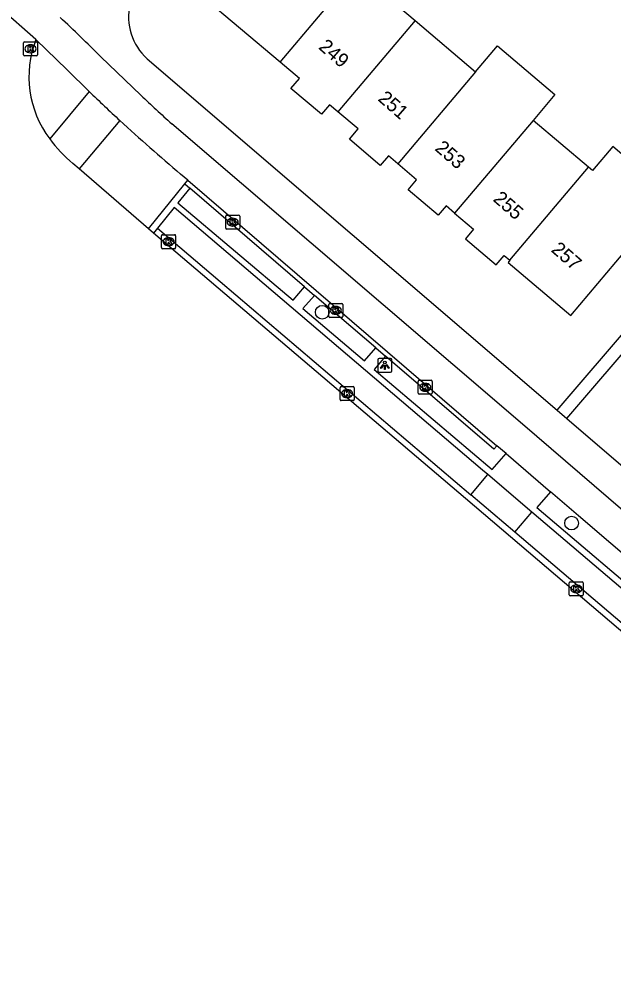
# Model space of a CAD drawing. Extents: x 162532 to 163264, y 381233 to 382042.
# Drawn here: x 162699.1 to 162741.6, y 381608.8 to 381676.6 of the extents above; entities that cross this region are included whole.
import ezdxf

# ---------------------------------------------------------------- set-up
doc = ezdxf.new("R2010")
doc.units = 0
for name, color, linetype in [('IMGEO_Berm_groen', 7, 'Continuous'), ('IMGEO_Berm_open', 7, 'Continuous'), ('IMGEO_Boom', 7, 'Continuous'), ('IMGEO_Fietspad_gesloten', 7, 'Continuous'), ('IMGEO_Groenvoorziening', 7, 'Continuous'), ('IMGEO_Kolk', 7, 'Continuous'), ('IMGEO_Lichtpunt', 7, 'Continuous'), ('IMGEO_Pand', 7, 'Continuous'), ('IMGEO_Pand_nummerreeks', 7, 'Continuous'), ('IMGEO_Parkeervlak_open', 7, 'Continuous'), ('IMGEO_Rijbaan_lokaal_gesloten', 7, 'Continuous'), ('IMGEO_Rijbaan_lokaal_open', 7, 'Continuous'), ('IMGEO_Voetpad_open', 7, 'Continuous')]:
    doc.layers.add(name, color=color, linetype=linetype)

msp = doc.modelspace()

# ---------------------------------------------------------------- linework, layer by layer
at = {"layer": 'IMGEO_Berm_groen'}
for points in [[(162719.505, 381657.491), (162711.294, 381664.536)], [(162724.61, 381653.11), (162720.224, 381656.874)], [(162733.256, 381646.123), (162733.039, 381645.878), (162725.293, 381652.525)]]:
    msp.add_lwpolyline(points, dxfattribs=at)
at = {"layer": 'IMGEO_Berm_open'}
for points in [[(162708.35, 381661.621), (162710.941, 381664.839)], [(162710.941, 381664.839), (162711.294, 381664.536)], [(162711.294, 381664.536), (162710.447, 381663.496), (162718.691, 381656.531), (162719.505, 381657.491)], [(162719.505, 381657.491), (162720.224, 381656.874)], [(162720.224, 381656.874), (162719.381, 381655.936), (162723.796, 381652.18), (162724.61, 381653.11)], [(162725.293, 381652.525), (162724.485, 381651.57), (162732.918, 381644.414), (162733.918, 381645.555)], [(162724.61, 381653.11), (162725.293, 381652.525)], [(162735.765, 381641.379), (162732.619, 381644.053)], [(162737.109, 381642.818), (162736.116, 381641.702), (162745.098, 381634.067), (162746.03, 381635.17)]]:
    msp.add_lwpolyline(points, dxfattribs=at)
at = {"layer": 'IMGEO_Boom'}
for centre in [(162720.767, 381655.666), (162738.609, 381640.586)]:
    msp.add_circle(centre, 0.489, dxfattribs=at)
at = {"layer": 'IMGEO_Fietspad_gesloten'}
for points in [[(162704.102, 381671.452), (162702.525, 381673.004), (162700.289, 381675.168)], [(162707.801, 381671.186), (162704.925, 381673.932)], [(162862.139, 381539.717), (162835.26, 381562.126), (162827.852, 381568.349), (162795.857, 381595.619), (162764.671, 381622.232), (162735.085, 381647.652), (162710.008, 381669.138)], [(162711.156, 381665.102), (162710.64, 381665.545)], [(162711.156, 381665.102), (162733.256, 381646.123)], [(162733.918, 381645.555), (162733.256, 381646.123)], [(162733.918, 381645.555), (162737.109, 381642.818)], [(162746.03, 381635.17), (162739.101, 381641.11), (162737.109, 381642.818)]]:
    msp.add_lwpolyline(points, dxfattribs=at)
for centre, radius, start, end in [((162633.194, 381602.874), 100.968, 44.73005, 47.02968), ((162794.077, 381764.47), 129.414, 225.95289, 227.29117), ((162783.492, 381750.54), 109.664, 226.35347, 227.92658), ((162792.908, 381763.14), 127.643, 227.27156, 229.87063)]:
    msp.add_arc(centre, radius, start, end, dxfattribs=at)
at = {"layer": 'IMGEO_Groenvoorziening'}
msp.add_lwpolyline([(162710.941, 381664.839), (162711.156, 381665.102)], dxfattribs=at)
at = {"layer": 'IMGEO_Kolk'}
for p, q in [((162699.404, 381674.081), (162699.404, 381674.933)), ((162699.479, 381675.007), (162700.331, 381675.007)), ((162700.405, 381674.933), (162700.405, 381674.081)), ((162699.915, 381674.227), (162699.89, 381674.227)), ((162699.892, 381674.787), (162699.917, 381674.787)), ((162700.331, 381674.007), (162699.479, 381674.007)), ((162713.864, 381661.68), (162713.864, 381662.532)), ((162713.939, 381662.606), (162714.791, 381662.606)), ((162714.352, 381662.386), (162714.377, 381662.386)), ((162714.865, 381662.532), (162714.865, 381661.68)), ((162714.791, 381661.606), (162713.939, 381661.606)), ((162714.375, 381661.826), (162714.35, 381661.826)), ((162709.285, 381660.286), (162709.285, 381661.138)), ((162709.36, 381661.212), (162710.212, 381661.212)), ((162709.773, 381660.992), (162709.798, 381660.992)), ((162710.286, 381661.138), (162710.286, 381660.286)), ((162710.212, 381660.212), (162709.36, 381660.212)), ((162709.796, 381660.432), (162709.771, 381660.432)), ((162721.239, 381655.373), (162721.239, 381656.225)), ((162721.314, 381656.299), (162722.166, 381656.299)), ((162721.727, 381656.079), (162721.752, 381656.079)), ((162722.24, 381656.225), (162722.24, 381655.373)), ((162722.166, 381655.299), (162721.314, 381655.299)), ((162721.75, 381655.519), (162721.725, 381655.519)), ((162727.641, 381649.872), (162727.641, 381650.724)), ((162727.716, 381650.798), (162728.568, 381650.798)), ((162728.129, 381650.578), (162728.154, 381650.578)), ((162728.642, 381650.724), (162728.642, 381649.872)), ((162722.051, 381649.418), (162722.051, 381650.27)), ((162722.126, 381650.344), (162722.978, 381650.344)), ((162722.539, 381650.124), (162722.564, 381650.124)), ((162723.052, 381650.27), (162723.052, 381649.418)), ((162728.568, 381649.798), (162727.716, 381649.798)), ((162728.152, 381650.018), (162728.127, 381650.018)), ((162722.978, 381649.344), (162722.126, 381649.344)), ((162722.562, 381649.564), (162722.537, 381649.564)), ((162738.442, 381635.461), (162738.442, 381636.313)), ((162738.517, 381636.387), (162739.369, 381636.387)), ((162739.443, 381636.313), (162739.443, 381635.461)), ((162738.953, 381635.607), (162738.928, 381635.607)), ((162738.93, 381636.167), (162738.955, 381636.167)), ((162739.369, 381635.387), (162738.517, 381635.387))]:
    msp.add_line(p, q, dxfattribs=at)
for points in [[(162699.404, 381674.081), (162699.404, 381674.933)], [(162699.479, 381675.007), (162700.331, 381675.007)], [(162700.405, 381674.933), (162700.405, 381674.081)], [(162699.725, 381674.707), (162699.848, 381674.707), (162699.848, 381674.556), (162699.978, 381674.707), (162700.142, 381674.707), (162699.996, 381674.556), (162700.149, 381674.307), (162699.997, 381674.307), (162699.912, 381674.471), (162699.848, 381674.404), (162699.848, 381674.307), (162699.725, 381674.307), (162699.725, 381674.707)], [(162700.331, 381674.007), (162699.479, 381674.007)], [(162713.864, 381661.68), (162713.864, 381662.532)], [(162713.939, 381662.606), (162714.791, 381662.606)], [(162714.185, 381662.306), (162714.308, 381662.306), (162714.308, 381662.155), (162714.438, 381662.306), (162714.602, 381662.306), (162714.456, 381662.155), (162714.609, 381661.906), (162714.457, 381661.906), (162714.372, 381662.07), (162714.308, 381662.003), (162714.308, 381661.906), (162714.185, 381661.906), (162714.185, 381662.306)], [(162714.865, 381662.532), (162714.865, 381661.68)], [(162714.791, 381661.606), (162713.939, 381661.606)], [(162709.285, 381660.286), (162709.285, 381661.138)], [(162709.36, 381661.212), (162710.212, 381661.212)], [(162709.606, 381660.912), (162709.729, 381660.912), (162709.729, 381660.761), (162709.859, 381660.912), (162710.023, 381660.912), (162709.877, 381660.761), (162710.03, 381660.512), (162709.878, 381660.512), (162709.793, 381660.676), (162709.729, 381660.609), (162709.729, 381660.512), (162709.606, 381660.512), (162709.606, 381660.912)], [(162710.286, 381661.138), (162710.286, 381660.286)], [(162710.212, 381660.212), (162709.36, 381660.212)], [(162721.239, 381655.373), (162721.239, 381656.225)], [(162721.314, 381656.299), (162722.166, 381656.299)], [(162721.56, 381655.999), (162721.683, 381655.999), (162721.683, 381655.848), (162721.813, 381655.999), (162721.977, 381655.999), (162721.831, 381655.848), (162721.984, 381655.599), (162721.832, 381655.599), (162721.747, 381655.763), (162721.683, 381655.696), (162721.683, 381655.599), (162721.56, 381655.599), (162721.56, 381655.999)], [(162722.24, 381656.225), (162722.24, 381655.373)], [(162722.166, 381655.299), (162721.314, 381655.299)], [(162727.641, 381649.872), (162727.641, 381650.724)], [(162727.716, 381650.798), (162728.568, 381650.798)], [(162727.962, 381650.498), (162728.085, 381650.498), (162728.085, 381650.347), (162728.215, 381650.498), (162728.379, 381650.498), (162728.233, 381650.347), (162728.386, 381650.098), (162728.234, 381650.098), (162728.149, 381650.262), (162728.085, 381650.195), (162728.085, 381650.098), (162727.962, 381650.098), (162727.962, 381650.498)], [(162728.642, 381650.724), (162728.642, 381649.872)], [(162722.051, 381649.418), (162722.051, 381650.27)], [(162722.126, 381650.344), (162722.978, 381650.344)], [(162722.372, 381650.044), (162722.495, 381650.044), (162722.495, 381649.893), (162722.625, 381650.044), (162722.789, 381650.044), (162722.643, 381649.893), (162722.796, 381649.644), (162722.644, 381649.644), (162722.559, 381649.808), (162722.495, 381649.741), (162722.495, 381649.644), (162722.372, 381649.644), (162722.372, 381650.044)], [(162723.052, 381650.27), (162723.052, 381649.418)], [(162728.568, 381649.798), (162727.716, 381649.798)], [(162722.978, 381649.344), (162722.126, 381649.344)], [(162738.442, 381635.461), (162738.442, 381636.313)], [(162738.517, 381636.387), (162739.369, 381636.387)], [(162739.443, 381636.313), (162739.443, 381635.461)], [(162738.763, 381636.087), (162738.886, 381636.087), (162738.886, 381635.936), (162739.016, 381636.087), (162739.18, 381636.087), (162739.034, 381635.936), (162739.187, 381635.687), (162739.035, 381635.687), (162738.95, 381635.851), (162738.886, 381635.784), (162738.886, 381635.687), (162738.763, 381635.687), (162738.763, 381636.087)], [(162739.369, 381635.387), (162738.517, 381635.387)]]:
    msp.add_lwpolyline(points, dxfattribs=at)
for centre, start, end in [((162699.481, 381674.931), 91.55205, 178.44795), ((162699.481, 381674.931), 91.55205, 178.44795), ((162700.329, 381674.931), 1.55205, 88.44795), ((162700.329, 381674.931), 1.55205, 88.44795), ((162699.481, 381674.083), 181.55205, 268.44795), ((162699.481, 381674.083), 181.55205, 268.44795), ((162700.329, 381674.083), 271.55205, 358.44795), ((162700.329, 381674.083), 271.55205, 358.44795), ((162713.941, 381662.53), 91.55205, 178.44795), ((162713.941, 381662.53), 91.55205, 178.44795), ((162714.789, 381662.53), 1.55205, 88.44795), ((162714.789, 381662.53), 1.55205, 88.44795), ((162713.941, 381661.682), 181.55205, 268.44795), ((162713.941, 381661.682), 181.55205, 268.44795), ((162714.789, 381661.682), 271.55205, 358.44795), ((162714.789, 381661.682), 271.55205, 358.44795), ((162709.362, 381661.136), 91.55205, 178.44795), ((162709.362, 381661.136), 91.55205, 178.44795), ((162710.21, 381661.136), 1.55205, 88.44795), ((162710.21, 381661.136), 1.55205, 88.44795), ((162709.362, 381660.288), 181.55205, 268.44795), ((162709.362, 381660.288), 181.55205, 268.44795), ((162710.21, 381660.288), 271.55205, 358.44795), ((162710.21, 381660.288), 271.55205, 358.44795), ((162721.316, 381656.223), 91.55205, 178.44795), ((162721.316, 381656.223), 91.55205, 178.44795), ((162722.164, 381656.223), 1.55205, 88.44795), ((162722.164, 381656.223), 1.55205, 88.44795), ((162721.316, 381655.375), 181.55205, 268.44795), ((162721.316, 381655.375), 181.55205, 268.44795), ((162722.164, 381655.375), 271.55205, 358.44795), ((162722.164, 381655.375), 271.55205, 358.44795), ((162727.718, 381650.722), 91.55205, 178.44795), ((162727.718, 381650.722), 91.55205, 178.44795), ((162728.566, 381650.722), 1.55205, 88.44795), ((162728.566, 381650.722), 1.55205, 88.44795), ((162722.128, 381650.268), 91.55205, 178.44795), ((162722.128, 381650.268), 91.55205, 178.44795), ((162722.976, 381650.268), 1.55205, 88.44795), ((162722.976, 381650.268), 1.55205, 88.44795), ((162727.718, 381649.874), 181.55205, 268.44795), ((162727.718, 381649.874), 181.55205, 268.44795), ((162728.566, 381649.874), 271.55205, 358.44795), ((162728.566, 381649.874), 271.55205, 358.44795), ((162722.128, 381649.42), 181.55205, 268.44795), ((162722.128, 381649.42), 181.55205, 268.44795), ((162722.976, 381649.42), 271.55205, 358.44795), ((162722.976, 381649.42), 271.55205, 358.44795), ((162738.519, 381636.311), 91.55205, 178.44795), ((162738.519, 381636.311), 91.55205, 178.44795), ((162739.367, 381636.311), 1.55205, 88.44795), ((162739.367, 381636.311), 1.55205, 88.44795), ((162738.519, 381635.463), 181.55205, 268.44795), ((162738.519, 381635.463), 181.55205, 268.44795), ((162739.367, 381635.463), 271.55205, 358.44795), ((162739.367, 381635.463), 271.55205, 358.44795)]:
    msp.add_arc(centre, 0.0765, start, end, dxfattribs=at)
for centre, major_axis, ratio, start_param, end_param in [((162699.891, 381674.507), (-0.387, 0.002), 0.722429, 4.712389, 7.853982), ((162699.916, 381674.507), (-0.39, 0.002), 0.717154, 1.570796, 4.712389), ((162714.351, 381662.106), (-0.387, 0.002), 0.722429, 4.712389, 7.853982), ((162714.376, 381662.106), (-0.39, 0.002), 0.717154, 1.570796, 4.712389), ((162709.772, 381660.712), (-0.387, 0.002), 0.722429, 4.712389, 7.853982), ((162709.797, 381660.712), (-0.39, 0.002), 0.717154, 1.570796, 4.712389), ((162721.726, 381655.799), (-0.387, 0.002), 0.722429, 4.712389, 7.853982), ((162721.751, 381655.799), (-0.39, 0.002), 0.717154, 1.570796, 4.712389), ((162728.128, 381650.298), (-0.387, 0.002), 0.722429, 4.712389, 7.853982), ((162728.153, 381650.298), (-0.39, 0.002), 0.717154, 1.570796, 4.712389), ((162722.538, 381649.844), (-0.387, 0.002), 0.722429, 4.712389, 7.853982), ((162722.563, 381649.844), (-0.39, 0.002), 0.717154, 1.570796, 4.712389), ((162738.929, 381635.887), (-0.387, 0.002), 0.722429, 4.712389, 7.853982), ((162738.954, 381635.887), (-0.39, 0.002), 0.717154, 1.570796, 4.712389)]:
    msp.add_ellipse(centre, major_axis=major_axis, ratio=ratio, start_param=start_param, end_param=end_param, dxfattribs=at)
at = {"layer": 'IMGEO_Lichtpunt'}
for p, q in [((162724.752, 381652.274), (162724.752, 381651.467)), ((162724.752, 381652.274), (162724.752, 381651.467)), ((162725.654, 381652.369), (162724.846, 381652.369)), ((162725.654, 381652.369), (162724.846, 381652.369)), ((162725.748, 381651.467), (162725.748, 381652.274)), ((162725.748, 381651.467), (162725.748, 381652.274)), ((162724.846, 381651.373), (162725.654, 381651.373)), ((162724.846, 381651.373), (162725.654, 381651.373))]:
    msp.add_line(p, q, dxfattribs=at)
for points in [[(162725.126, 381651.938), (162725.165, 381651.91), (162724.977, 381651.648), (162724.939, 381651.675), (162725.126, 381651.938)], [(162725.228, 381651.89), (162725.275, 381651.89), (162725.275, 381651.568), (162725.228, 381651.568), (162725.228, 381651.89)], [(162725.338, 381651.91), (162725.376, 381651.937), (162725.563, 381651.675), (162725.524, 381651.647), (162725.338, 381651.91)]]:
    msp.add_lwpolyline(points, dxfattribs=at)
msp.add_circle((162725.251, 381652.072), 0.0994, dxfattribs=at)
for centre, start, end in [((162724.846, 381652.274), 90, 180), ((162724.846, 381652.274), 90, 180), ((162725.654, 381652.274), 0, 90), ((162725.654, 381652.274), 0, 90), ((162724.846, 381651.467), 180, 270), ((162724.846, 381651.467), 180, 270), ((162725.654, 381651.467), 270, 0), ((162725.654, 381651.467), 270, 360)]:
    msp.add_arc(centre, 0.0946, start, end, dxfattribs=at)
at = {"layer": 'IMGEO_Pand'}
for points in [[(162717.755, 381673.553), (162712.092, 381678.341), (162714.62, 381681.331), (162715.341, 381680.722), (162718.301, 381684.224), (162718.606, 381683.966), (162720.453, 381686.15), (162724.905, 381682.387), (162723.059, 381680.202), (162723.243, 381680.046)], [(162717.755, 381673.553), (162723.243, 381680.046)], [(162723.243, 381680.046), (162727.408, 381676.524)], [(162727.408, 381676.524), (162721.888, 381670)], [(162727.408, 381676.524), (162731.744, 381672.859)], [(162731.744, 381672.859), (162733.311, 381674.713), (162737.42, 381671.239), (162735.853, 381669.386)], [(162721.888, 381670), (162721.295, 381670.502), (162720.723, 381669.825), (162718.534, 381671.675), (162719.135, 381672.387), (162717.755, 381673.553)], [(162731.744, 381672.859), (162726.175, 381666.28)], [(162726.175, 381666.28), (162725.502, 381666.849), (162724.926, 381666.166), (162722.718, 381668.033), (162723.342, 381668.771), (162721.888, 381670)], [(162735.853, 381669.386), (162730.243, 381662.747)], [(162739.813, 381666.036), (162735.853, 381669.386)], [(162734.192, 381659.387), (162734.06, 381659.23), (162738.552, 381655.433), (162741.781, 381659.252), (162744.306, 381662.238), (162745.757, 381663.953), (162741.549, 381667.51), (162740.099, 381665.794), (162739.813, 381666.036)], [(162730.243, 381662.747), (162729.629, 381663.266), (162729.067, 381662.601), (162726.913, 381664.422), (162727.521, 381665.142), (162726.175, 381666.28)], [(162734.192, 381659.387), (162739.813, 381666.036)], [(162730.243, 381662.747), (162731.6, 381661.6), (162731.02, 381660.914), (162733.224, 381659.05), (162733.793, 381659.724), (162734.192, 381659.387)]]:
    msp.add_lwpolyline(points, dxfattribs=at)
at = {"layer": 'IMGEO_Parkeervlak_open'}
for points in [[(162732.619, 381644.053), (162732.233, 381644.381), (162710.172, 381663.149), (162708.984, 381661.688)], [(162731.402, 381642.611), (162732.619, 381644.053)], [(162734.552, 381639.929), (162735.765, 381641.379)], [(162761.85, 381619.211), (162761.709, 381619.331), (162735.765, 381641.379)]]:
    msp.add_lwpolyline(points, dxfattribs=at)
at = {"layer": 'IMGEO_Rijbaan_lokaal_gesloten'}
for points in [[(162700.289, 381675.168), (162695.064, 381679.762)], [(162703.383, 381665.914), (162702.936, 381666.297)], [(162708.35, 381661.621), (162703.383, 381665.914)], [(162708.69, 381661.323), (162708.35, 381661.621)], [(162838.874, 381550.696), (162834.758, 381554.093), (162791.516, 381590.924), (162760.162, 381617.53), (162731.009, 381642.342), (162708.69, 381661.323)]]:
    msp.add_lwpolyline(points, dxfattribs=at)
for centre, radius, start, end in [((162707.131, 381672.501), 7.343, 158.70321, 217.11376), ((162709.612, 381674.216), 10.358, 216.39706, 229.86686)]:
    msp.add_arc(centre, radius, start, end, dxfattribs=at)
at = {"layer": 'IMGEO_Rijbaan_lokaal_open'}
for points in [[(162708.984, 381661.688), (162708.69, 381661.323)], [(162708.984, 381661.688), (162731.402, 381642.611)], [(162734.552, 381639.929), (162731.402, 381642.611)], [(162760.637, 381617.746), (162734.552, 381639.929)]]:
    msp.add_lwpolyline(points, dxfattribs=at)
at = {"layer": 'IMGEO_Voetpad_open'}
for points in [[(162737.568, 381648.656), (162753.805, 381667.586), (162749.306, 381671.531), (162746.943, 381673.752), (162743.853, 381676.657), (162743.574, 381676.361), (162742.497, 381677.285), (162743.712, 381678.731)], [(162708.247, 381673.791), (162737.568, 381648.656)], [(162704.102, 381671.452), (162701.275, 381668.07)], [(162706.299, 381669.376), (162703.383, 381665.914)], [(162738.266, 381648.058), (162754.502, 381666.987), (162759.577, 381662.635), (162759.544, 381662.595)], [(162737.568, 381648.656), (162738.266, 381648.058)], [(162738.266, 381648.058), (162797.068, 381597.652), (162800.385, 381594.834)]]:
    msp.add_lwpolyline(points, dxfattribs=at)
msp.add_arc((162710.92, 381676.765), 3.999, 166.69254, 228.04567, dxfattribs=at)

# ---------------------------------------------------------------- texts
at = {"layer": 'IMGEO_Pand_nummerreeks'}
for s, rotation, p in [('249', 318.93404, (162720.451, 381674.547)), ('251', 318.93404, (162724.695, 381670.849)), ('253', 318.93404, (162728.77, 381667.299)), ('255', 318.93611, (162732.929, 381663.675)), ('257', 318.93611, (162737.088, 381660.05))]:
    msp.add_text(s, height=1, rotation=rotation, dxfattribs=at).set_placement(p)

doc.saveas('drawing.dxf')
